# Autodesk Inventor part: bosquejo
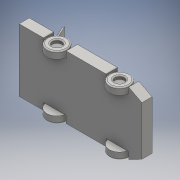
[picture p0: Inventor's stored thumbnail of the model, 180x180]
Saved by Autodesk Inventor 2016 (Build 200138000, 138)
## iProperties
Created: 2017-05
Part Number: bosquejo
Material: Generic
Document SubType Name: Modeling
Designer: laboratorioesan
Density: 1 g/cm^3
Appearance: Default
Author: laboratorioesan
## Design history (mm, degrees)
sketch "Sketch1"
  geometry: L1 (0, 0)-(-103.779, 0); L2 (-103.779, 0)-(-103.779, -29.217); L3 (-103.779, -29.217)-(-199.385, -29.217); L4 (-199.385, -29.217)-(-199.385, 0); L5 (-199.385, 0)-(-368.75, 0); L6 (-368.75, 0)-(-368.75, -29.217); L7 (-368.75, -29.217)-(-464.356, -29.217); L8 (-464.356, -29.217)-(-464.356, 0); L9 (-520.233, -29.217)-(-520.233, -237.101); L10 (-464.356, -266.318)-(-464.356, -237.101); L11 (-464.356, -237.101)-(-368.75, -237.101); L12 (-368.75, -237.101)-(-368.75, -266.318); L13 (-199.385, -266.318)-(-368.75, -266.318); L14 (-199.385, -266.318)-(-199.385, -237.101); L15 (-199.385, -237.101)-(-103.779, -237.101); L16 (-103.779, -237.101)-(-103.779, -266.318); L17 (-103.779, -266.318)-(0, -266.318); L18 (0, -266.318)-(0, 0); L19 (-464.356, -266.318)-(-520.233, -237.101); L20 (-464.356, 0)-(-520.233, -29.217)
  constraints: 40 end point, 10 perpendicular, 10 point on line, 6 horizontal alignment, 5 equal length, 1 horizontal, 1 vertical
extrude "Extrusion1" new body sketch "Sketch1" distance "d0" = 18; taper "d1" = 0 deg
sketch "Sketch4"
  geometry: L1 (0, 0)-(103.779, 0) reference; L2 (103.779, 0)-(103.779, 29.217) reference; L3 (103.779, 29.217)-(199.385, 29.217) reference; L4 (199.385, 29.217)-(199.385, 0) reference; L5 (199.385, 0)-(368.75, 0) reference; L6 (368.75, 0)-(368.75, 29.217) reference; L7 (368.75, 29.217)-(464.356, 29.217) reference; L8 (464.356, 29.217)-(464.356, 0) reference; L9 (464.356, 0)-(520.233, 29.217) reference; L10 (520.233, 29.217)-(520.233, 237.101) reference; L11 (520.233, 237.101)-(464.356, 266.318) reference; L12 (464.356, 266.318)-(464.356, 237.101) reference; L13 (464.356, 237.101)-(368.75, 237.101) reference; L14 (368.75, 237.101)-(368.75, 266.318) reference; L15 (368.75, 266.318)-(199.385, 266.318) reference; L16 (199.385, 266.318)-(199.385, 237.101) reference; L17 (199.385, 237.101)-(103.779, 237.101) reference; L18 (103.779, 237.101)-(103.779, 266.318) reference; L19 (103.779, 266.318)-(0, 266.318) reference; L20 (0, 266.318)-(0, 0) reference; L21 (6, 260.318)-(97.779, 260.318); L22 (97.779, 260.318)-(97.779, 237.101); L23 (205.385, 237.101)-(205.385, 260.318); L24 (205.385, 260.318)-(362.75, 260.318); L25 (362.75, 260.318)-(362.75, 237.101); L26 (464.356, 259.547)-(514.233, 233.467); L27 (514.233, 233.467)-(514.233, 32.851); L28 (514.233, 32.851)-(464.356, 6.771); L29 (362.75, 29.217)-(362.75, 6); L30 (362.75, 6)-(205.385, 6); L31 (205.385, 6)-(205.385, 29.217); L32 (97.779, 29.217)-(97.779, 6); L33 (97.779, 6)-(6, 6); L34 (6, 6)-(6, 260.318); L35 (103.779, 237.101)-(97.779, 237.101); L36 (199.385, 237.101)-(103.779, 237.101) reference; L37 (199.385, 237.101)-(205.385, 237.101); L38 (103.779, 0)-(103.779, 29.217) reference; L39 (103.779, 29.217)-(97.779, 29.217); L40 (199.385, 29.217)-(205.385, 29.217); L41 (368.75, 29.217)-(464.356, 29.217) reference; L42 (368.75, 29.217)-(362.75, 29.217); L43 (464.356, 237.101)-(368.75, 237.101) reference; L44 (368.75, 237.101)-(362.75, 237.101); 1 further point
  constraints: 40 end point, 5 point on line, 3 perpendicular, 1 other
  dimensions: "d5" = 6 distance between parallel lines of L19 L21
extrude "Extrusion3" join sketch "Sketch4" distance "d6" = 25; taper "d7" = 0 deg
sketch "Sketch5"
  geometry: L1 (0, 0)-(95.606, 0) reference; L2 (95.606, 0)-(95.606, 18) reference; L3 (0, 18)-(95.606, 18) reference; L4 (0, 0)-(0, 18) reference; L5 (264.971, 0)-(360.577, 0) reference; L6 (360.577, 0)-(360.577, 18) reference; L7 (264.971, 18)-(360.577, 18) reference; L8 (264.971, 0)-(264.971, 18) reference; L9 (95.606, 0)-(264.971, 0) reference; L10 (264.971, 0)-(264.971, 43) reference; L11 (95.606, 43)-(264.971, 43) reference; L12 (95.606, 0)-(95.606, 43) reference; L13 (-97.779, 18)-(-6, 18) reference; L14 (-103.779, 0)-(0, 0) reference; L15 (0, 0)-(0, 43) reference; L16 (-103.779, 43)-(0, 43) reference; L17 (-103.779, 0)-(-103.779, 43) reference; L18 (360.577, 0)-(416.454, 0) reference; L19 (416.454, 0)-(416.454, 43) reference; L20 (360.577, 43)-(416.454, 43) reference; L21 (360.577, 0)-(360.577, 43) reference; C1 r 42.5 at (47.803, 9); C2 r 42.5 at (312.774, 9); C3 r 20 at (47.803, 9); C4 r 20 at (312.774, 9); 3 further points
  constraints: 4 centre point, 2 coincident, 2 midpoint, 2 vertical alignment, 1 equal radius
  dimensions: "d8" = 85 diameter of C2; "d9" = 40 diameter of C3; "d10" = 40 diameter of C4
extrude "Extrusion4" join sketch "Sketch5" stored distance "d11" = 25; taper "d12" = 0 deg
sketch "Sketch6"
  geometry: L1 (0, 18)-(35.721, 18) reference; L2 (0, 0)-(35.721, 0) reference; L3 (264.971, 0)-(300.692, 0) reference; L4 (264.971, 18)-(300.692, 18) reference; A1 r 20 centre (17.861, 9) between (35.721, 0) and (35.721, 18) reference; A2 r 20 centre (17.861, 9) between (0, 18) and (0, 0) reference; A3 r 20 centre (282.832, 9) between (264.971, 18) and (264.971, 0) reference; A4 r 20 centre (282.832, 9) between (300.692, 0) and (300.692, 18) reference; A5 r 20 centre (17.861, 9) between (35.721, 0) and (35.721, 18) reference; A6 r 20 centre (282.832, 9) between (264.971, 18) and (264.971, 0) reference; 1 further point
extrude "Extrusion5" join sketch "Sketch6" distance "d14" = 15; taper "d15" = 0 deg
workplane "Work Plane1"
mirror "Mirror1"
mirror "Mirror2"
fillet "Fillet2" dims "d16" = 5
sketch "Sketch7"
  geometry: L1 (163.365, 0)-(6, 0) reference; L2 (163.365, 0)-(163.365, 25) reference; L3 (6, 25)-(163.365, 25) reference; L4 (6, 0)-(6, 25) reference; L5 (169.365, -18)-(0, -18) reference; L6 (0, -18)-(0, 25) reference; L7 (169.365, 25)-(0, 25) reference; L8 (169.365, -18)-(169.365, 25) reference; L9 (-43.536, 0)-(68.185, 96.214); L10 (68.185, 96.214)-(74.059, 89.394); L11 (74.059, 89.394)-(-29.744, 0); L12 (-43.536, 0)-(-29.744, 0); 1 further point
  constraints: 8 end point, 1 horizontal, 1 horizontal alignment, 1 parallel, 1 perpendicular
  dimensions: "d18" = 9 distance of L9.end L10.end
extrude "Extrusion6" join sketch "Sketch7" stored distance "d19" = 222; taper "d20" = 0 deg
sketch "Sketch8"
  geometry: L1 (0, 207.884)-(119.265, 207.884) reference; L2 (0, 0)-(0, 207.884) reference; L3 (119.265, 0)-(0, 0) reference; L4 (147.441, 0)-(119.265, 0) reference; L5 (147.441, 207.884)-(147.441, 0) reference; L6 (119.265, 207.884)-(147.441, 207.884) reference; L7 (0, 0)-(0, 207.884) reference; L8 (0, 0)-(119.265, 0); L9 (119.265, 0)-(119.265, 39.115); L10 (119.265, 39.115)-(0, 39.115); L11 (0, 39.115)-(0, 0); L12 (0, 207.884)-(119.265, 207.884); L13 (119.265, 207.884)-(119.265, 168.768); L14 (119.265, 168.768)-(0, 168.768); L15 (0, 168.768)-(0, 207.884); 1 further point
  constraints: 16 end point, 4 parallel, 2 horizontal, 2 perpendicular, 1 collinear, 1 point on line
extrude "Extrusion7" cut sketch "Sketch8" distance "d21" = 15; taper "d22" = 0 deg
fillet "Fillet3" dims "d23" = 10
sketch "Sketch9"
  geometry: L1 (0, -9)-(0, 0) reference; L2 (99.265, -9)-(0, -9) reference; L3 (99.265, 0)-(99.265, -9) reference; L4 (0, 0)-(99.265, 0) reference; L5 (0, 0)-(99.265, 0) reference; L6 (91.515, -9)-(10.062, -103.593); L7 (-21.682, -37.959)-(-16.933, -42.049) reference; L8 (-16.933, -42.049)-(-5.187, -28.41) reference; L9 (-9.936, -24.32)-(-5.187, -28.41) reference; L10 (118.6, -135.015)-(-0.641, -32.325) reference; L11 (-5.187, -28.41)-(-9.936, -24.32) reference; L12 (40.742, -67.964)-(-9.936, -24.32); L13 (-9.936, -24.32)-(3.258, -9); L14 (3.258, -9)-(91.515, -9); L15 (0, -9)-(99.265, -9) reference; A1 r 42.5 centre (-47.282, -4.035) between (-21.682, -37.959) and (-9.936, -24.32) reference; 1 further point
  constraints: 8 end point, 4 point on line, 1 collinear, 1 perpendicular
extrude "Extrusion8" join sketch "Sketch9" stored distance "d24" = 109.5; taper "d25" = 0 deg
workplane "Work Plane2"
sketch "Sketch10"
  geometry: L1 (75.222, 24.912)-(69.349, 18.092) reference; L2 (0.005, 89.688)-(75.222, 24.912) reference; L3 (-5.868, 82.869)-(0.005, 89.688) reference; L4 (0.005, 77.812)-(-5.868, 82.869) reference; L5 (0.005, 77.812)-(0, 0) reference; L6 (66.88, 0)-(0, 0) reference; L7 (66.88, 0)-(66.88, 20.218) reference; L8 (69.349, 18.092)-(66.88, 20.218) reference; L9 (0.005, 77.812)-(-5.868, 82.869) reference; L10 (69.349, 18.092)-(66.88, 20.218) reference; L11 (66.88, 20.218)-(0.005, 77.812); L12 (-5.868, 82.869)-(-13.445, 89.394) reference; 1 further point
  constraints: 2 end point, 1 collinear
extrude "Extrusion9" cut sketch "Sketch10" stored distance "d26" = 120; taper "d27" = 0 deg
sketch "Sketch11"
  geometry: L1 (-6.267, 0)-(0, 0) reference; L2 (0, 0)-(0, 18) reference; L3 (-6.267, 18)-(0, 18) reference; L4 (-95.606, 18)-(-89.339, 18) reference; L5 (-95.606, 0)-(-95.606, 18) reference; L6 (-95.606, 0)-(-89.339, 0) reference; L7 (-101.606, 18)-(-193.385, 18) reference; L8 (-101.606, 18)-(-101.606, 43) reference; L9 (-193.385, 43)-(-101.606, 43) reference; L10 (-193.385, 18)-(-193.385, 43) reference; L11 (163.365, 18)-(6, 18) reference; L12 (163.365, 18)-(163.365, 43) reference; L13 (6, 43)-(163.365, 43) reference; L14 (6, 18)-(6, 43) reference; L15 (-11.399, 18)-(-84.207, 18) reference; L16 (-101.606, 18)-(-193.385, 18) reference; L17 (-121.238, 18)-(13.704, 18); L18 (13.704, 18)-(13.704, 27.596); L19 (13.704, 27.596)-(-121.238, 27.596); L20 (-121.238, 27.596)-(-121.238, 18); L21 (101.18, 114.214)-(108.757, 107.688) reference; L22 (101.18, 114.214)-(95.307, 107.394) reference; L23 (-121.238, 114.214)-(-80.368, 27.596); L24 (-86.019, 27.596)-(-123.672, 107.394); L25 (-121.238, 114.214)-(-123.672, 107.394); A1 r 42.5 centre (-47.803, 9) between (-6.267, 0) and (-6.267, 18) reference; A2 r 42.5 centre (-47.803, 9) between (-89.339, 18) and (-89.339, 0) reference; A3 r 37.5 centre (-47.803, 9) between (-11.399, 18) and (-84.207, 18) reference; A4 r 37.5 centre (-47.803, 9) between (-84.207, 18) and (-11.399, 18) reference; A5 r 42.5 centre (-47.803, 9) between (-6.267, 18) and (-89.339, 18) reference; 1 further point
  constraints: 14 end point, 3 parallel, 3 point on line, 2 point on circle, 1 horizontal, 1 perpendicular
extrude "Extrusion10" join sketch "Sketch11" stored distance "d28" = 120; taper "d29" = 0 deg
sketch "Sketch12"
  geometry: L1 (199.385, 29.217)-(199.385, 0) reference; L2 (199.385, 0)-(368.75, 0) reference; L3 (368.75, 0)-(368.75, 29.217) reference; L4 (368.75, 29.217)-(362.75, 29.217) reference; L5 (362.75, 29.217)-(362.75, 6) reference; L6 (362.75, 6)-(205.385, 6) reference; L7 (205.385, 6)-(205.385, 29.217) reference; L8 (205.385, 29.217)-(199.385, 29.217) reference; L9 (368.75, 237.101)-(368.75, 266.318) reference; L10 (368.75, 266.318)-(199.385, 266.318) reference; L11 (199.385, 266.318)-(199.385, 237.101) reference; L12 (199.385, 237.101)-(205.385, 237.101) reference; L13 (205.385, 237.101)-(205.385, 260.318) reference; L14 (205.385, 260.318)-(362.75, 260.318) reference; L15 (362.75, 260.318)-(362.75, 237.101) reference; L16 (362.75, 237.101)-(368.75, 237.101) reference; L17 (368.75, 237.101)-(368.75, 266.318) reference; L18 (368.75, 237.101)-(199.385, 237.101); L19 (199.385, 237.101)-(199.385, 266.318); L20 (199.385, 266.318)-(368.75, 266.318); L21 (368.75, 266.318)-(368.75, 237.101); L22 (199.385, 0)-(368.75, 0) reference; L23 (368.75, 29.217)-(199.385, 29.217); L24 (199.385, 29.217)-(199.385, 0); L25 (199.385, 0)-(368.75, 0); L26 (368.75, 0)-(368.75, 29.217); 1 further point
  constraints: 16 end point, 4 parallel, 2 horizontal, 2 perpendicular
extrude "Extrusion11" join sketch "Sketch12" distance "d30" = 5; taper "d31" = 0 deg
body "Solid1"
node "Projected Loop3"
node "Projected Loop4"
node "Projected Loop5"
node "Projected Loop6"
node "Projected Loop7"
node "Projected Loop8"
node "Projected Loop9"
node "Projected Loop10"
node "Projected Loop11"
node "Projected Loop12"
node "Projected Loop13"
node "Projected Loop14"
node "Projected Loop15"
node "Projected Loop16"
node "Projected Loop17"
node "Projected Loop18"
node "Projected Loop19"
node "Projected Loop20"
node "Projected Loop21"
node "Projected Loop22"
node "Projected Loop23"
